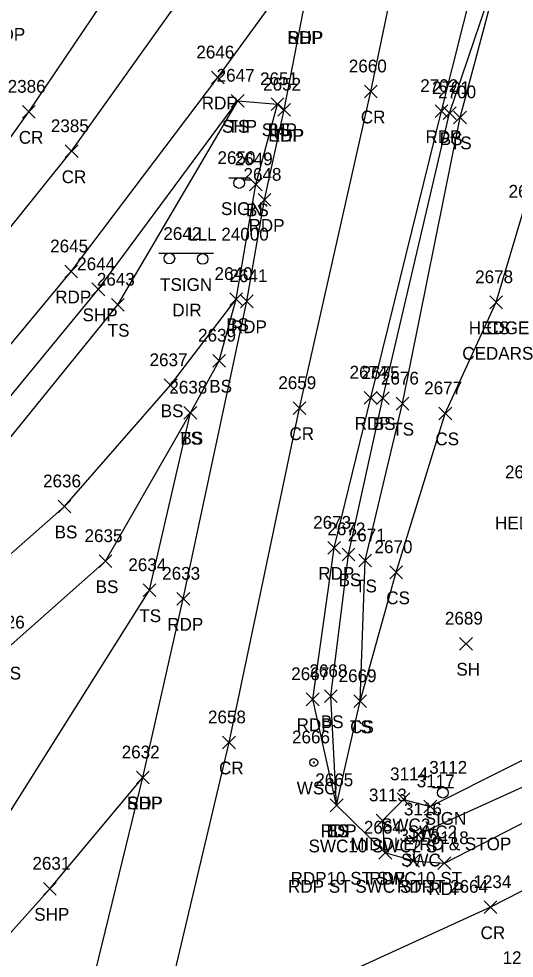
# Model space of a CAD drawing. Extents: x 1477930 to 1480780, y 774090 to 784647.
# Drawn here: x 1479397 to 1479474.7, y 774710.6 to 774857.9 of the extents above; entities that cross this region are included whole.
import ezdxf

# ---------------------------------------------------------------- set-up
doc = ezdxf.new("R2010")
doc.units = 0
for name, color, linetype in [('L_A', 7, 'Continuous'), ('L_C', 7, 'Continuous'), ('L_I', 7, 'Continuous'), ('L_TIC', 7, 'Continuous'), ('LAHR', 7, 'Continuous'), ('LELB', 7, 'Continuous'), ('P_A', 7, 'Continuous'), ('P_I', 7, 'Continuous'), ('P_TIC', 7, 'Continuous'), ('PET', 7, 'Continuous'), ('PRC', 7, 'Continuous'), ('PSP', 7, 'Continuous'), ('R_A', 7, 'Continuous'), ('R_I', 7, 'Continuous'), ('R_TIC', 7, 'Continuous'), ('RSW', 7, 'Continuous'), ('S_A', 7, 'Continuous'), ('S_C', 7, 'Continuous'), ('S_I', 7, 'Continuous'), ('SSGN', 7, 'Continuous'), ('U_A', 7, 'Continuous'), ('U_I', 7, 'Continuous'), ('UWV', 7, 'Continuous')]:
    doc.layers.add(name, color=color, linetype=linetype)

msp = doc.modelspace()

# ---------------------------------------------------------------- linework, layer by layer
at = {"layer": 'L_TIC'}
for points in [[(1479430.34, 774844.03), (1479432.34, 774846.03)], [(1479432.34, 774844.03), (1479430.34, 774846.03)], [(1479436.58, 774843.49), (1479438.58, 774845.49)], [(1479438.58, 774843.49), (1479436.58, 774845.49)], [(1479463.58, 774842.08), (1479465.58, 774844.08)], [(1479465.58, 774842.08), (1479463.58, 774844.08)], [(1479465.21, 774841.43), (1479467.21, 774843.43)], [(1479467.21, 774841.43), (1479465.21, 774843.43)], [(1479433.19, 774830.92), (1479435.19, 774832.92)], [(1479435.19, 774830.92), (1479433.19, 774832.92)], [(1479430.1, 774812.94), (1479432.1, 774814.94)], [(1479432.1, 774812.94), (1479430.1, 774814.94)], [(1479430.1, 774812.94), (1479432.1, 774814.94)], [(1479432.1, 774812.94), (1479430.1, 774814.94)], [(1479411.56, 774812.05), (1479413.56, 774814.05)], [(1479413.56, 774812.05), (1479411.56, 774814.05)], [(1479470.89, 774812.44), (1479472.89, 774814.44)], [(1479472.89, 774812.44), (1479470.89, 774814.44)], [(1479470.89, 774812.44), (1479472.89, 774814.44)], [(1479472.89, 774812.44), (1479470.89, 774814.44)], [(1479427.44, 774803.28), (1479429.44, 774805.28)], [(1479429.44, 774803.28), (1479427.44, 774805.28)], [(1479419.83, 774799.43), (1479421.83, 774801.43)], [(1479421.83, 774799.43), (1479419.83, 774801.43)], [(1479453.09, 774797.42), (1479455.09, 774799.42)], [(1479455.09, 774797.42), (1479453.09, 774799.42)], [(1479422.92, 774795.13), (1479424.92, 774797.13)], [(1479424.92, 774795.13), (1479422.92, 774797.13)], [(1479422.92, 774795.13), (1479424.92, 774797.13)], [(1479424.92, 774795.13), (1479422.92, 774797.13)], [(1479456.17, 774796.55), (1479458.17, 774798.55)], [(1479458.17, 774796.55), (1479456.17, 774798.55)], [(1479462.9, 774795.02), (1479464.9, 774797.02)], [(1479464.9, 774795.02), (1479462.9, 774797.02)], [(1479403.19, 774780.43), (1479405.19, 774782.43)], [(1479405.19, 774780.43), (1479403.19, 774782.43)], [(1479409.62, 774771.85), (1479411.62, 774773.85)], [(1479411.62, 774771.85), (1479409.62, 774773.85)], [(1479447.72, 774772.92), (1479449.72, 774774.92)], [(1479449.72, 774772.92), (1479447.72, 774774.92)], [(1479450.35, 774771.96), (1479452.35, 774773.96)], [(1479452.35, 774771.96), (1479450.35, 774773.96)], [(1479455.2, 774770.11), (1479457.2, 774772.11)], [(1479457.2, 774770.11), (1479455.2, 774772.11)], [(1479416.5, 774767.3), (1479418.5, 774769.3)], [(1479418.5, 774767.3), (1479416.5, 774769.3)], [(1479466.15, 774758.91), (1479468.15, 774760.91)], [(1479468.15, 774758.91), (1479466.15, 774760.91)], [(1479444.94, 774750.68), (1479446.94, 774752.68)], [(1479446.94, 774750.68), (1479444.94, 774752.68)], [(1479449.54, 774749.89), (1479451.54, 774751.89)], [(1479451.54, 774749.89), (1479449.54, 774751.89)], [(1479449.54, 774749.89), (1479451.54, 774751.89)], [(1479451.54, 774749.89), (1479449.54, 774751.89)], [(1479445.86, 774733.58), (1479447.86, 774735.58)], [(1479447.86, 774733.58), (1479445.86, 774735.58)], [(1479445.86, 774733.58), (1479447.86, 774735.58)], [(1479447.86, 774733.58), (1479445.86, 774735.58)]]:
    msp.add_lwpolyline(points, dxfattribs=at)
at = {"layer": 'LAHR'}
msp.add_lwpolyline([(1479471.89, 774813.44), (1479479.66, 774839.55)], dxfattribs=at)
at = {"layer": 'LELB'}
for points in [[(1479446.86, 774734.58), (1479450.54, 774750.89), (1479451.35, 774772.96), (1479457.17, 774797.55), (1479466.21, 774842.43), (1479473.3, 774868.84), (1479477.85, 774880.64), (1479486.95, 774912.8)], [(1479446.86, 774734.58), (1479445.94, 774751.68), (1479448.72, 774773.92), (1479454.09, 774798.42), (1479464.58, 774843.08), (1479473.3, 774868.84), (1479482.11, 774878.4), (1479495.75, 774910.51)], [(1479239.1, 774628.15), (1479242.92, 774638.24), (1479276.86, 774668.3), (1479306.94, 774697.73), (1479319.53, 774710.27), (1479351.31, 774740.09), (1479380.37, 774773.44), (1479412.56, 774813.05), (1479431.34, 774845.03)], [(1479239.1, 774628.15), (1479244.5, 774634.75), (1479251.92, 774639.74), (1479281.73, 774661.2), (1479312.11, 774684.66), (1479326.98, 774697.03), (1479330.87, 774704.88), (1479332.01, 774709.04), (1479352.65, 774720.44), (1479359.43, 774730.67), (1479387.65, 774766.89), (1479404.19, 774781.43), (1479420.83, 774800.43), (1479431.1, 774813.94), (1479434.19, 774831.92), (1479437.58, 774844.49)], [(1479244.5, 774634.75), (1479252.74, 774637.23), (1479275, 774646.05), (1479317.84, 774674.82), (1479348.56, 774695.39), (1479367.95, 774720.93), (1479395.36, 774759.3), (1479410.62, 774772.85), (1479423.92, 774796.13), (1479428.44, 774804.28), (1479431.1, 774813.94)], [(1479450.54, 774750.89), (1479456.2, 774771.11), (1479463.9, 774796.02), (1479471.89, 774813.44)], [(1479244.5, 774634.75), (1479253.67, 774635.16), (1479275, 774646.05), (1479321.56, 774665.78), (1479350.31, 774685.54), (1479389.05, 774723.2), (1479417.5, 774768.3), (1479423.92, 774796.13)]]:
    msp.add_lwpolyline(points, dxfattribs=at)
at = {"layer": 'P_TIC'}
for points in [[(1479427.23, 774847.68), (1479429.23, 774849.68)], [(1479429.23, 774847.68), (1479427.23, 774849.68)], [(1479451.21, 774845.49), (1479453.21, 774847.49)], [(1479453.21, 774845.49), (1479451.21, 774847.49)], [(1479430.34, 774844.03), (1479432.34, 774846.03)], [(1479432.34, 774844.03), (1479430.34, 774846.03)], [(1479397.58, 774842.3), (1479399.58, 774844.3)], [(1479399.58, 774842.3), (1479397.58, 774844.3)], [(1479436.58, 774843.49), (1479438.58, 774845.49)], [(1479438.58, 774843.49), (1479436.58, 774845.49)], [(1479437.63, 774842.63), (1479439.63, 774844.63)], [(1479439.63, 774842.63), (1479437.63, 774844.63)], [(1479437.63, 774842.63), (1479439.63, 774844.63)], [(1479439.63, 774842.63), (1479437.63, 774844.63)], [(1479462.31, 774842.41), (1479464.31, 774844.41)], [(1479464.31, 774842.41), (1479462.31, 774844.41)], [(1479404.3, 774836.12), (1479406.3, 774838.12)], [(1479406.3, 774836.12), (1479404.3, 774838.12)], [(1479434.56, 774828.5), (1479436.56, 774830.5)], [(1479436.56, 774828.5), (1479434.56, 774830.5)], [(1479404.23, 774817.27), (1479406.23, 774819.27)], [(1479406.23, 774817.27), (1479404.23, 774819.27)], [(1479408.48, 774814.47), (1479410.48, 774816.47)], [(1479410.48, 774814.47), (1479408.48, 774816.47)], [(1479431.79, 774812.6), (1479433.79, 774814.6)], [(1479433.79, 774812.6), (1479431.79, 774814.6)], [(1479451.2, 774797.48), (1479453.2, 774799.48)], [(1479453.2, 774797.48), (1479451.2, 774799.48)], [(1479440.03, 774795.84), (1479442.03, 774797.84)], [(1479442.03, 774795.84), (1479440.03, 774797.84)], [(1479445.48, 774773.94), (1479447.48, 774775.94)], [(1479447.48, 774773.94), (1479445.48, 774775.94)], [(1479421.81, 774765.95), (1479423.81, 774767.95)], [(1479423.81, 774765.95), (1479421.81, 774767.95)], [(1479442.1, 774750.2), (1479444.1, 774752.2)], [(1479444.1, 774750.2), (1479442.1, 774752.2)], [(1479428.98, 774743.43), (1479430.98, 774745.43)], [(1479430.98, 774743.43), (1479428.98, 774745.43)], [(1479415.46, 774737.94), (1479417.46, 774739.94)], [(1479417.46, 774737.94), (1479415.46, 774739.94)], [(1479415.46, 774737.94), (1479417.46, 774739.94)], [(1479417.46, 774737.94), (1479415.46, 774739.94)], [(1479445.86, 774733.58), (1479447.86, 774735.58)], [(1479447.86, 774733.58), (1479445.86, 774735.58)], [(1479453.49, 774726.13), (1479455.49, 774728.13)], [(1479455.49, 774726.13), (1479453.49, 774728.13)], [(1479457.85, 774724.87), (1479459.85, 774726.87)], [(1479459.85, 774724.87), (1479457.85, 774726.87)], [(1479462.75, 774724.49), (1479464.75, 774726.49)], [(1479464.75, 774724.49), (1479462.75, 774726.49)], [(1479400.89, 774720.48), (1479402.89, 774722.48)], [(1479402.89, 774720.48), (1479400.89, 774722.48)], [(1479470, 774717.6), (1479472, 774719.6)], [(1479472, 774717.6), (1479470, 774719.6)]]:
    msp.add_lwpolyline(points, dxfattribs=at)
at = {"layer": 'PET'}
for points in [[(1479231.31, 774636.06), (1479272.54, 774672.78), (1479302.99, 774702.6), (1479344.22, 774746.86), (1479373.44, 774780.01), (1479405.23, 774818.27), (1479428.23, 774848.68), (1479447.93, 774875.75), (1479460.71, 774894.51), (1479479.69, 774925.18), (1479480.31, 774927.38), (1479493.45, 774951.2), (1479514.74, 775006.53), (1479531.7, 775055.13), (1479548.14, 775106.72), (1479553.83, 775125.43), (1479564.45, 775161.29), (1479573.74, 775193.3), (1479576.58, 775204.25), (1479585.43, 775238.68), (1479593.96, 775273.34), (1479599.4, 775295.6)], [(1479458.85, 774725.87), (1479463.75, 774725.49), (1479503.78, 774746.04), (1479529.26, 774759.88), (1479547.26, 774769.69), (1479593.15, 774794.19), (1479638.49, 774817.33), (1479672.22, 774835.12), (1479713.57, 774857.96), (1479753.19, 774879.74), (1479794.61, 774902.46), (1479830.33, 774920.88), (1479861.74, 774937.83), (1479877.76, 774946.85), (1479905.13, 774960.92), (1479936.65, 774977.61), (1479958.81, 774989.4), (1479973, 774995.93), (1480008.35, 775014.95)], [(1479454.49, 774727.13), (1479446.86, 774734.58), (1479443.1, 774751.2), (1479446.48, 774774.94), (1479452.2, 774798.48), (1479463.31, 774843.41), (1479471.87, 774877.48), (1479481.52, 774912.36)], [(1479234.45, 774632.83), (1479239.1, 774628.15), (1479289.14, 774648.12), (1479321.9, 774663.73), (1479351.45, 774679.08), (1479366.99, 774687.18), (1479407.96, 774704.03), (1479416.46, 774738.94), (1479422.81, 774766.95), (1479432.79, 774813.6), (1479435.56, 774829.5), (1479438.63, 774843.63), (1479441.63, 774858.96), (1479447.93, 774875.75)]]:
    msp.add_lwpolyline(points, dxfattribs=at)
at = {"layer": 'PRC'}
for points in [[(1480015.89, 775005.87), (1479971.79, 774982.46), (1479929.14, 774959.03), (1479892.61, 774942.34), (1479860.44, 774925.31), (1479806.49, 774896.54), (1479658.45, 774815.54), (1479643.75, 774807.57), (1479597.62, 774782.97), (1479555.61, 774761.16), (1479513.42, 774740.32), (1479471, 774718.6), (1479432.73, 774701.1), (1479418.32, 774694.97), (1479344.83, 774660.92), (1479298.6, 774640.39), (1479262.12, 774624.4), (1479219.63, 774609.01), (1479186.74, 774593.83)], [(1479194.24, 774620.68), (1479224.8, 774645.46), (1479270.23, 774685.77), (1479304.81, 774721.63), (1479337.5, 774760.88), (1479368.49, 774801.2), (1479398.58, 774843.3), (1479429.86, 774889.66)], [(1479418.32, 774694.97), (1479429.98, 774744.43), (1479441.03, 774796.84), (1479452.21, 774846.49), (1479460.29, 774885.01)], [(1479304.81, 774721.63), (1479339.94, 774758.98), (1479373.28, 774797.31), (1479405.3, 774837.12), (1479437.9, 774882.86)]]:
    msp.add_lwpolyline(points, dxfattribs=at)
at = {"layer": 'PSP'}
for points in [[(1479234.45, 774632.83), (1479231.31, 774636.06), (1479275.79, 774669.49), (1479305.63, 774698.93), (1479347.8, 774743.57), (1479377.2, 774776.25), (1479409.48, 774815.47), (1479431.34, 774845.03), (1479437.58, 774844.49), (1479438.63, 774843.63)], [(1479366.99, 774687.18), (1479386.11, 774703.86), (1479401.89, 774721.48), (1479416.46, 774738.94)]]:
    msp.add_lwpolyline(points, dxfattribs=at)
at = {"layer": 'R_TIC'}
for points in [[(1479456.36, 774734.51), (1479458.36, 774736.51)], [(1479458.36, 774734.51), (1479456.36, 774736.51)], [(1479460.55, 774733.41), (1479462.55, 774735.41)], [(1479462.55, 774733.41), (1479460.55, 774735.41)], [(1479453.05, 774731.2), (1479455.05, 774733.2)], [(1479455.05, 774731.2), (1479453.05, 774733.2)], [(1479453.05, 774731.2), (1479455.05, 774733.2)], [(1479455.05, 774731.2), (1479453.05, 774733.2)], [(1479458.6, 774729), (1479460.6, 774731)], [(1479460.6, 774729), (1479458.6, 774731)], [(1479453.49, 774726.13), (1479455.49, 774728.13)], [(1479455.49, 774726.13), (1479453.49, 774728.13)], [(1479457.85, 774724.87), (1479459.85, 774726.87)], [(1479459.85, 774724.87), (1479457.85, 774726.87)]]:
    msp.add_lwpolyline(points, dxfattribs=at)
at = {"layer": 'RSW'}
for points in [[(1479454.05, 774732.2), (1479457.36, 774735.51), (1479461.55, 774734.41), (1479499.97, 774753.7), (1479531.62, 774770.46), (1479545.78, 774777.94), (1479596.7, 774804.86), (1479626.34, 774821.05), (1479665.84, 774842.34), (1479709.72, 774866.29), (1479748.23, 774887.23), (1479790.98, 774910.55), (1479825.88, 774929.42), (1479857.89, 774946.35), (1479880.81, 774958.36), (1479898.02, 774967.81), (1479932.31, 774985.56), (1479966.42, 775003.67), (1480005.03, 775023.74)], [(1479458.85, 774725.87), (1479459.6, 774730), (1479502.04, 774749.23), (1479530.65, 774764.31), (1479546.64, 774772.58), (1479592.5, 774796.78), (1479632.83, 774818.63), (1479668.4, 774838.36), (1479711.89, 774862.21), (1479750.54, 774883.44), (1479792.95, 774906.12), (1479828.15, 774924.96), (1479859.81, 774941.82), (1479882.29, 774953.43), (1479899.45, 774962.93), (1479935.39, 774981.77), (1479958.84, 774993.68), (1479967.68, 774998.52), (1480006.53, 775018.83)], [(1479454.49, 774727.13), (1479454.05, 774732.2)], [(1479458.85, 774725.87), (1479454.49, 774727.13)]]:
    msp.add_lwpolyline(points, dxfattribs=at)
at = {"layer": 'SSGN'}
for p, q in [((1479429.94, 774832.97), (1479433.27, 774832.97)), ((1479431.58, 774832.14), (1479431.58, 774832.14)), ((1479418.97, 774821.14), (1479427.57, 774821.14)), ((1479422.99, 774820.24), (1479422.99, 774820.24)), ((1479461.88, 774737.38), (1479465.21, 774737.38)), ((1479463.52, 774736.55), (1479463.52, 774736.55))]:
    msp.add_line(p, q, dxfattribs=at)
for centre in [(1479431.58, 774832.14), (1479420.63, 774820.31), (1479425.85, 774820.24), (1479463.52, 774736.55)]:
    msp.add_circle(centre, 0.833, dxfattribs=at)
at = {"layer": 'UWV'}
for radius in [0.625, 0.0833]:
    msp.add_circle((1479443.27, 774741.29), radius, dxfattribs=at)

# ---------------------------------------------------------------- texts
at = {"layer": 'L_A'}
for s, p in [('TS', (1479429.75, 774840.03)), ('BS', (1479436.02, 774839.49)), ('BS', (1479463.03, 774838.08)), ('TS', (1479464.62, 774837.43)), ('BS', (1479432.64, 774826.92)), ('BS', (1479429.54, 774808.94)), ('BS', (1479429.54, 774808.94)), ('HEDGE', (1479467.59, 774808.44)), ('CS', (1479470.33, 774808.44)), ('TS', (1479410.96, 774808.05)), ('BS', (1479426.88, 774799.28)), ('BS', (1479419.27, 774795.43)), ('BS', (1479452.53, 774793.42)), ('TS', (1479455.58, 774792.55)), ('TS', (1479422.33, 774791.13)), ('BS', (1479422.36, 774791.13)), ('CS', (1479462.34, 774791.02)), ('HEDGE', (1479471.71, 774777.85)), ('BS', (1479402.63, 774776.43)), ('BS', (1479447.16, 774768.92)), ('BS', (1479409.06, 774767.85)), ('TS', (1479449.76, 774767.96)), ('CS', (1479454.64, 774766.11)), ('TS', (1479415.91, 774763.3)), ('BS', (1479393.8, 774754.3)), ('SH', (1479465.64, 774754.91)), ('BS', (1479444.38, 774746.68)), ('TS', (1479448.95, 774745.89)), ('CS', (1479448.98, 774745.89)), ('TS', (1479445.27, 774729.58)), ('BS', (1479445.3, 774729.58))]:
    msp.add_text(s, height=2, dxfattribs=at).set_placement(p)
at = {"layer": 'L_C'}
msp.add_text('CEDARS', height=2, dxfattribs=at).set_placement((1479466.56, 774804.44))
at = {"layer": 'L_I'}
for s, p in [('2647', (1479428.04, 774848.03)), ('2651', (1479434.84, 774847.49)), ('2701', (1479461.81, 774846.08)), ('2700', (1479462.78, 774845.43)), ('2649', (1479430.88, 774834.92)), ('2643', (1479409.25, 774816.05)), ('2640', (1479427.71, 774816.94)), ('2640', (1479427.71, 774816.94)), ('2678', (1479468.58, 774816.44)), ('2678', (1479468.58, 774816.44)), ('2639', (1479425.13, 774807.28)), ('2637', (1479417.52, 774803.43)), ('2675', (1479450.78, 774801.42)), ('2676', (1479453.81, 774800.55)), ('2638', (1479420.62, 774799.13)), ('2638', (1479420.62, 774799.13)), ('2677', (1479460.59, 774799.02)), ('2681', (1479473.26, 774785.85)), ('2636', (1479400.82, 774784.43)), ('2672', (1479445.41, 774776.92)), ('2671', (1479448.61, 774775.96)), ('2635', (1479407.32, 774775.85)), ('2670', (1479452.8, 774774.11)), ('2634', (1479414.19, 774771.3)), ('2689', (1479463.84, 774762.91)), ('2626', (1479391.99, 774762.3)), ('2668', (1479442.59, 774754.68)), ('2669', (1479447.17, 774753.89)), ('2669', (1479447.17, 774753.89)), ('2665', (1479443.51, 774737.58)), ('2665', (1479443.51, 774737.58))]:
    msp.add_text(s, height=2, dxfattribs=at).set_placement(p)
at = {"layer": 'P_A'}
for s, p in [('RDP', (1479392.37, 774854.45)), ('SHP', (1479439.17, 774853.96)), ('RDP', (1479439.12, 774853.96)), ('RDP', (1479425.71, 774843.68)), ('CR', (1479450.65, 774841.49)), ('SHP', (1479428.88, 774840.03)), ('SHP', (1479435.12, 774839.49)), ('CR', (1479397.01, 774838.3)), ('SHP', (1479436.17, 774838.63)), ('RDP', (1479436.12, 774838.63)), ('RDP', (1479460.79, 774838.41)), ('CR', (1479403.73, 774832.12)), ('RDP', (1479433.04, 774824.5)), ('RDP', (1479402.72, 774813.27)), ('SHP', (1479407.01, 774810.47)), ('RDP', (1479430.27, 774808.6)), ('RDP', (1479449.69, 774793.48)), ('CR', (1479439.46, 774791.84)), ('RDP', (1479443.97, 774769.94)), ('RDP', (1479420.29, 774761.95)), ('RDP', (1479440.58, 774746.2)), ('CR', (1479428.42, 774739.43)), ('SHP', (1479414, 774733.94)), ('RDP', (1479413.95, 774733.94)), ('RDP', (1479444.35, 774729.58)), ('RDP', (1479451.97, 774722.13)), ('RDP', (1479456.34, 774720.87)), ('RDP', (1479461.24, 774720.49)), ('SHP', (1479399.43, 774716.48)), ('CR', (1479469.43, 774713.6))]:
    msp.add_text(s, height=2, dxfattribs=at).set_placement(p)
at = {"layer": 'P_I'}
for s, p in [('2646', (1479424.86, 774851.68)), ('2660', (1479448.77, 774849.49)), ('2647', (1479428.04, 774848.03)), ('2651', (1479434.84, 774847.49)), ('2386', (1479395.27, 774846.3)), ('2652', (1479435.33, 774846.63)), ('2652', (1479435.33, 774846.63)), ('2702', (1479459.97, 774846.41)), ('2385', (1479402.04, 774840.12)), ('2648', (1479432.25, 774832.5)), ('2645', (1479401.93, 774821.27)), ('2644', (1479406.17, 774818.47)), ('2641', (1479430.05, 774816.6)), ('2674', (1479448.89, 774801.48)), ('2659', (1479437.71, 774799.84)), ('2673', (1479443.18, 774777.94)), ('2633', (1479419.5, 774769.95)), ('2667', (1479439.74, 774754.2)), ('2658', (1479426.68, 774747.43)), ('2632', (1479413.15, 774741.94)), ('2632', (1479413.15, 774741.94)), ('2665', (1479443.51, 774737.58)), ('2664', (1479451.13, 774730.13)), ('3115', (1479456.72, 774728.87)), ('3118', (1479461.62, 774728.49)), ('2631', (1479399.15, 774724.48)), ('1234', (1479468.31, 774721.6)), ('1235', (1479472.88, 774709.69))]:
    msp.add_text(s, height=2, dxfattribs=at).set_placement(p)
at = {"layer": 'R_A'}
for s, p in [('SWC2', (1479453.83, 774730.51)), ('SWC2', (1479458.02, 774729.41)), ('SWC10 SWC2 ST', (1479442.45, 774727.2)), ('SWC10 SWC2 ST', (1479442.45, 774727.2)), ('SWC', (1479456.96, 774725)), ('RDP10 ST SWC10 ST', (1479439.63, 774722.13)), ('RDP ST SWC ST JT 2664', (1479439.24, 774720.87))]:
    msp.add_text(s, height=2, dxfattribs=at).set_placement(p)
at = {"layer": 'R_I'}
for s, p in [('3114', (1479455.24, 774738.51)), ('3117', (1479459.42, 774737.41)), ('3113', (1479451.92, 774735.2)), ('3113', (1479451.92, 774735.2)), ('3116', (1479457.42, 774733)), ('2664', (1479451.13, 774730.13)), ('3115', (1479456.72, 774728.87))]:
    msp.add_text(s, height=2, dxfattribs=at).set_placement(p)
at = {"layer": 'S_A'}
for s, p in [('SIGN', (1479428.72, 774827.12)), ('TSIGN', (1479419.17, 774815.22)), ('SIGN', (1479460.66, 774731.53))]:
    msp.add_text(s, height=2, dxfattribs=at).set_placement(p)
at = {"layer": 'S_C'}
for s, p in [('LLL 24000', (1479423.57, 774823.12)), ('DIR', (1479421.09, 774811.22)), ('MIDDLE RD & STOP', (1479448.99, 774727.53))]:
    msp.add_text(s, height=2, dxfattribs=at).set_placement(p)
at = {"layer": 'S_I'}
for s, p in [('2650', (1479428.17, 774835.12)), ('2642', (1479419.68, 774823.22)), ('3112', (1479461.38, 774739.53))]:
    msp.add_text(s, height=2, dxfattribs=at).set_placement(p)
at = {"layer": 'U_A'}
msp.add_text('WSO', height=2, dxfattribs=at).set_placement((1479440.6, 774736.29))
at = {"layer": 'U_I'}
for s, p in [('2699', (1479473.82, 774829.85)), ('2666', (1479439.86, 774744.29))]:
    msp.add_text(s, height=2, dxfattribs=at).set_placement(p)

doc.saveas('drawing.dxf')
